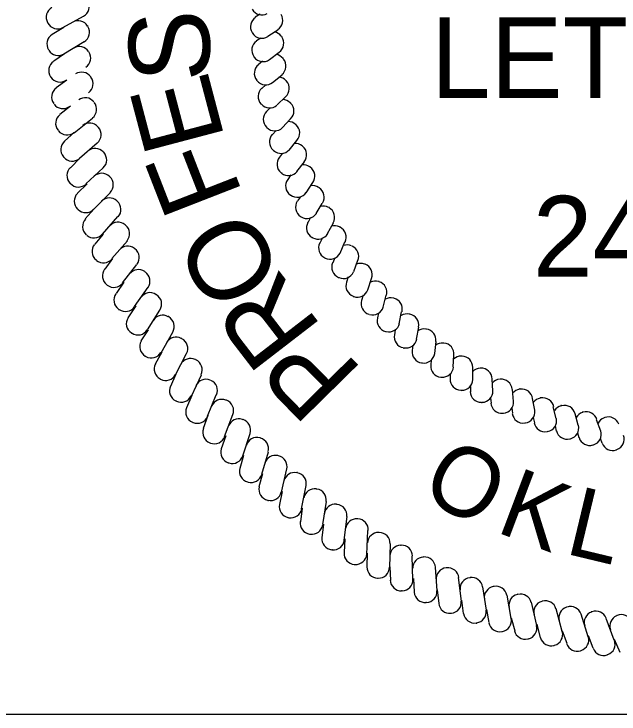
# Model space of a CAD drawing. Extents: x 2121385 to 2181200, y 132498 to 161273.
# Drawn here: x 2164147 to 2165083, y 136441 to 137524 of the extents above; entities that cross this region are included whole.
import ezdxf

# ---------------------------------------------------------------- set-up
doc = ezdxf.new("R2010")
doc.units = 0
doc.layers.add('SHT_Stamp_PE', color=7, linetype='Continuous')
doc.layers.add('SHT_Standard_Sheet_Lines', color=7, linetype='Continuous')

msp = doc.modelspace()

# ---------------------------------------------------------------- linework, layer by layer
at = {"layer": 'SHT_Stamp_PE'}
for p, q in [((2164528.1, 137523.1), (2164520.7, 137518.5)), ((2164222.8, 137502.9), (2164254.9, 137520.4)), ((2164199, 137510.3), (2164199.9, 137509.4)), ((2164224.6, 137502.9), (2164206.3, 137491.9)), ((2164262.2, 137504.8), (2164261.3, 137504.8)), ((2164516.1, 137494.7), (2164516.1, 137493.8)), ((2164540, 137489.2), (2164555.6, 137499.3)), ((2164224.6, 137461.7), (2164255.8, 137480.9)), ((2164529, 137486.4), (2164522.6, 137481.9)), ((2164562, 137488.3), (2164561.1, 137489.2)), ((2164200.8, 137468.1), (2164200.8, 137468.1)), ((2164225.6, 137461.7), (2164209.1, 137450.7)), ((2164518, 137458), (2164518.9, 137457.1)), ((2164542.7, 137453.4), (2164557.4, 137464.4)), ((2164531.7, 137450.7), (2164525.3, 137445.2)), ((2164563.8, 137454.4), (2164563.8, 137455.3)), ((2164203.6, 137426.9), (2164204.5, 137425.9)), ((2164547.3, 137417.7), (2164562, 137429.6)), ((2164229.2, 137421.4), (2164212.7, 137409.4)), ((2164522.6, 137421.4), (2164523.5, 137420.4)), ((2164537.2, 137414), (2164530.8, 137408.5)), ((2164569.3, 137419.5), (2164568.4, 137420.4)), ((2164554.6, 137382.9), (2164567.5, 137395.7)), ((2164209.1, 137384.7), (2164209.1, 137384.7)), ((2164234.7, 137381), (2164218.2, 137368.2)), ((2164529, 137384.7), (2164529.9, 137383.8)), ((2164575.7, 137385.6), (2164574.8, 137386.5)), ((2164543.6, 137378.3), (2164538.1, 137372.8)), ((2164240.2, 137339.8), (2164268.6, 137362.7)), ((2164562.9, 137348), (2164575.7, 137361.8)), ((2164277.8, 137348), (2164276.9, 137348.9)), ((2164584, 137352.6), (2164583.1, 137352.6)), ((2164215.5, 137343.4), (2164216.4, 137343.4)), ((2164241.1, 137340.7), (2164225.6, 137326.9)), ((2164538.1, 137348), (2164539.1, 137348)), ((2164552.8, 137343.4), (2164547.3, 137337)), ((2164573, 137313.2), (2164584.9, 137327.9)), ((2164248.5, 137300.4), (2164276, 137324.2)), ((2164594.1, 137318.7), (2164593.1, 137319.6)), ((2164286.1, 137309.5), (2164285.1, 137310.4)), ((2164548.2, 137313.2), (2164549.1, 137312.3)), ((2164562.9, 137308.6), (2164558.3, 137302.2)), ((2164223.7, 137302.2), (2164224.6, 137302.2)), ((2164249.4, 137300.4), (2164234.7, 137285.7)), ((2164584.9, 137280.2), (2164596.8, 137294.9)), ((2164258.6, 137260.9), (2164285.1, 137285.7)), ((2164606, 137286.6), (2164605.1, 137287.5)), ((2164561.1, 137278.4), (2164561.1, 137277.4)), ((2164575.7, 137274.7), (2164571.1, 137267.4)), ((2164296.1, 137271.9), (2164295.2, 137271.9)), ((2164599.6, 137247.2), (2164609.6, 137262.8)), ((2164233.8, 137261.9), (2164234.7, 137260.9)), ((2164260.4, 137260.9), (2164245.7, 137246.3)), ((2164619.7, 137254.5), (2164618.8, 137255.4)), ((2164270.5, 137221.5), (2164296.1, 137247.2)), ((2164574.8, 137243.5), (2164575.7, 137243.5)), ((2164590.4, 137240.8), (2164585.8, 137234.4)), ((2164307.1, 137234.4), (2164306.2, 137234.4)), ((2164615.1, 137215.1), (2164624.3, 137230.7)), ((2164245.7, 137222.4), (2164246.6, 137221.5)), ((2164271.4, 137222.4), (2164257.6, 137206.9)), ((2164635.3, 137224.3), (2164634.4, 137224.3)), ((2164284.2, 137183), (2164308.1, 137210.5)), ((2164591.3, 137210.5), (2164591.3, 137209.6)), ((2164606, 137208.7), (2164602.3, 137201.4)), ((2164320, 137196.8), (2164319.1, 137197.7)), ((2164632.6, 137183.9), (2164641.7, 137200.4)), ((2164651.8, 137194), (2164650.9, 137194)), ((2164259.5, 137182.1), (2164259.5, 137182.1)), ((2164285.1, 137183), (2164272.3, 137167.4)), ((2164608.7, 137178.4), (2164609.6, 137177.5)), ((2164624.3, 137176.6), (2164620.6, 137169.3)), ((2164298.9, 137145.4), (2164322.7, 137172.9)), ((2164651.8, 137153.7), (2164659.1, 137171.1)), ((2164670.1, 137164.7), (2164670.1, 137164.7)), ((2164334.6, 137160.1), (2164333.7, 137161)), ((2164274.1, 137143.6), (2164275.1, 137142.7)), ((2164299.8, 137145.4), (2164287.9, 137128.9)), ((2164628, 137146.4), (2164628.9, 137146.4)), ((2164643.6, 137146.4), (2164640.8, 137139)), ((2164315.4, 137107.9), (2164337.4, 137136.3)), ((2164672.9, 137125.3), (2164679.3, 137142.7)), ((2164690.3, 137136.3), (2164689.4, 137137.2)), ((2164350.2, 137124.4), (2164350.2, 137125.3)), ((2164649.1, 137116.1), (2164650.9, 137116.1)), ((2164664.6, 137117), (2164661.9, 137108.8)), ((2164694.9, 137096.9), (2164700.4, 137114.3)), ((2164290.6, 137105.1), (2164291.6, 137104.2)), ((2164317.2, 137108.8), (2164305.3, 137091.4)), ((2164333.7, 137071.2), (2164354.8, 137101.4)), ((2164712.3, 137109.7), (2164711.4, 137109.7)), ((2164367.6, 137089.5), (2164366.7, 137089.5)), ((2164672, 137086.8), (2164672.9, 137086.8)), ((2164687.6, 137088.6), (2164684.8, 137080.4)), ((2164718.7, 137070.3), (2164723.3, 137088.6)), ((2164735.2, 137084), (2164734.3, 137084)), ((2164335.6, 137072.1), (2164323.6, 137053.8)), ((2164309, 137066.6), (2164309.9, 137066.6)), ((2164353.9, 137035.4), (2164373.1, 137065.7)), ((2164696.7, 137059.3), (2164696.7, 137059.3)), ((2164711.4, 137061.1), (2164709.6, 137053.8)), ((2164743.5, 137044.6), (2164747.1, 137062.9)), ((2164760, 137059.3), (2164759.1, 137059.3)), ((2164386.9, 137055.6), (2164386, 137055.6)), ((2164354.8, 137035.4), (2164343.8, 137018)), ((2164737.1, 137035.4), (2164736.1, 137027.2)), ((2164770.1, 137020.8), (2164773.7, 137039.1)), ((2164785.6, 137036.4), (2164784.7, 137036.4)), ((2164329.1, 137029.9), (2164330.1, 137029.9)), ((2164375, 136999.7), (2164393.3, 137031.8)), ((2164722.4, 137032.7), (2164723.3, 137032.7)), ((2164407.1, 137021.7), (2164406.1, 137021.7)), ((2164798.5, 136998.8), (2164800.3, 137017.1)), ((2164812.2, 137014.4), (2164811.3, 137014.4)), ((2164749.9, 137007), (2164750.8, 137007)), ((2164764.6, 137011.6), (2164763.6, 137003.4)), ((2164350.2, 136994.2), (2164351.1, 136994.2)), ((2164375.9, 137000.6), (2164365.8, 136982.3)), ((2164397, 136965.8), (2164414.4, 136998.8)), ((2164826.9, 136977.7), (2164827.8, 136996)), ((2164840.6, 136994.2), (2164839.7, 136994.2)), ((2164429.1, 136988.7), (2164428.1, 136989.6)), ((2164778.3, 136984.1), (2164779.2, 136984.1)), ((2164793, 136988.7), (2164792.1, 136980.4)), ((2164857.1, 136958.4), (2164857.1, 136976.8)), ((2164870, 136975.9), (2164869.1, 136975.9)), ((2164373.1, 136959.4), (2164374.1, 136958.4)), ((2164397.9, 136966.7), (2164389.6, 136947.4)), ((2164421.7, 136932.8), (2164437.3, 136965.8)), ((2164807.6, 136962.1), (2164808.6, 136962.1)), ((2164822.3, 136967.6), (2164822.3, 136959.4)), ((2164888.3, 136940.1), (2164887.4, 136959.4)), ((2164452, 136956.6), (2164451.1, 136957.5)), ((2164899.3, 136958.4), (2164899.3, 136958.4)), ((2164838.8, 136941), (2164839.7, 136941.9)), ((2164853.5, 136947.4), (2164853.5, 136939.2)), ((2164920.4, 136924.5), (2164918.6, 136942.9)), ((2164930.5, 136943.8), (2164929.6, 136943.8)), ((2164422.6, 136933.7), (2164414.4, 136914.4)), ((2164446.5, 136901.6), (2164460.2, 136934.6)), ((2164475.8, 136926.4), (2164474.9, 136926.4)), ((2164884.6, 136930), (2164885.6, 136921.8)), ((2164953.4, 136910.8), (2164949.7, 136929.1)), ((2164962.6, 136930), (2164961.6, 136930)), ((2164397.9, 136925.4), (2164398.8, 136925.4)), ((2164870.9, 136922.7), (2164871.8, 136922.7)), ((2164986.4, 136897.9), (2164981.8, 136916.3)), ((2164994.6, 136918.1), (2164993.7, 136918.1)), ((2164903.9, 136906.2), (2164904.8, 136906.2)), ((2164917.6, 136914.4), (2164918.6, 136906.2)), ((2165020.3, 136887.9), (2165015.7, 136905.3)), ((2165027.6, 136908), (2165026.7, 136908)), ((2164447.4, 136902.5), (2164440.1, 136882.4)), ((2164473.1, 136870.4), (2164485.9, 136904.4)), ((2164501.5, 136896.1), (2164500.6, 136897)), ((2164950.6, 136899.8), (2164952.5, 136891.5)), ((2165055.1, 136878.7), (2165048.7, 136896.1)), ((2165061.6, 136899.8), (2165060.6, 136898.9)), ((2164423.6, 136892.4), (2164424.5, 136891.5)), ((2164937.8, 136891.5), (2164938.7, 136891.5)), ((2164984.6, 136886.9), (2164986.4, 136878.7)), ((2164501.5, 136840.2), (2164512.5, 136875)), ((2164972.6, 136877.8), (2164973.6, 136878.7)), ((2165019.4, 136875.9), (2165021.2, 136868.6)), ((2164474.9, 136871.4), (2164467.6, 136851.2)), ((2164529, 136867.7), (2164528.1, 136868.6)), ((2165007.5, 136866.8), (2165008.4, 136866.8)), ((2165054.2, 136867.7), (2165057, 136860.4)), ((2164450.1, 136860.4), (2164451.1, 136860.4)), ((2165043.2, 136856.7), (2165044.1, 136857.6)), ((2164502.4, 136841.1), (2164496.9, 136820.9)), ((2164530.8, 136811.8), (2164540.9, 136846.6)), ((2164556.5, 136840.2), (2164555.6, 136841.1)), ((2165079, 136849.4), (2165079.9, 136850.3)), ((2164478.6, 136830.1), (2164479.5, 136829.2)), ((2164561.1, 136784.3), (2164569.3, 136820)), ((2164531.7, 136812.7), (2164526.2, 136792.5)), ((2164585.8, 136814.5), (2164584.9, 136814.5)), ((2164508.8, 136799.9), (2164509.7, 136799.9)), ((2164592.2, 136758.6), (2164599.6, 136794.4)), ((2164616.1, 136788.9), (2164615.1, 136788.9)), ((2164562, 136785.2), (2164558.3, 136765)), ((2164540, 136771.4), (2164540.9, 136771.4)), ((2164625.2, 136733.9), (2164630.7, 136769.6)), ((2164647.2, 136765), (2164646.3, 136765)), ((2164593.1, 136759.5), (2164590.4, 136738.4)), ((2164571.1, 136744.9), (2164572.1, 136744.9)), ((2164658.2, 136710), (2164662.8, 136746.7)), ((2164679.3, 136743), (2164678.4, 136743)), ((2164626.1, 136734.8), (2164623.4, 136713.7)), ((2164693.1, 136688), (2164694.9, 136724.7)), ((2164712.3, 136721.9), (2164711.4, 136721.9)), ((2164605.1, 136719.2), (2164606, 136719.2)), ((2164659.1, 136711.9), (2164658.2, 136690.8)), ((2164728.8, 136667.9), (2164729.7, 136704.5)), ((2164746.2, 136701.8), (2164745.3, 136701.8)), ((2164639, 136695.4), (2164639.9, 136695.4)), ((2164694, 136689.9), (2164693.1, 136668.8)), ((2164764.6, 136648.6), (2164763.6, 136685.3)), ((2164781.1, 136683.4), (2164780.1, 136683.4)), ((2164673.8, 136672.4), (2164674.7, 136672.4)), ((2164728.8, 136668.8), (2164729.7, 136647.7)), ((2164802.1, 136632.1), (2164799.4, 136667.9)), ((2164816.8, 136666.9), (2164815.9, 136666.9)), ((2164709.6, 136651.4), (2164710.5, 136651.4)), ((2164765.5, 136650.4), (2164766.4, 136629.4)), ((2164839.7, 136615.6), (2164835.1, 136652.3)), ((2164852.6, 136652.3), (2164852.6, 136651.4)), ((2164878.2, 136601.9), (2164872.7, 136637.6)), ((2164890.1, 136638.5), (2164889.2, 136638.5)), ((2164747.1, 136632.1), (2164748.1, 136632.1)), ((2164802.1, 136633), (2164804.9, 136611.9)), ((2164916.7, 136589), (2164910.3, 136624.8)), ((2164926.8, 136626.6), (2164925.9, 136625.7)), ((2164784.7, 136613.8), (2164785.6, 136613.8)), ((2164839.7, 136617.4), (2164842.5, 136596.4)), ((2164956.1, 136578), (2164947.9, 136613.8)), ((2164965.3, 136615.6), (2164964.4, 136615.6)), ((2164878.2, 136602.8), (2164881.9, 136582.6)), ((2164995.6, 136568.9), (2164986.4, 136603.7)), ((2165002.9, 136606.4), (2165002, 136606.4)), ((2164823.2, 136597.3), (2164824.1, 136597.3)), ((2165035.9, 136560.6), (2165024.9, 136595.4)), ((2165041.4, 136599.1), (2165040.5, 136599.1)), ((2165080.8, 136593.6), (2165079.9, 136593.6)), ((2164862.6, 136581.7), (2164863.6, 136581.7)), ((2164916.7, 136589.9), (2164922.2, 136569.8)), ((2165076.2, 136555.1), (2165063.4, 136589)), ((2164956.1, 136579.9), (2164961.6, 136558.8)), ((2164995.6, 136569.8), (2165002.9, 136550.5)), ((2164902.1, 136568.9), (2164903, 136568.9)), ((2165035.9, 136562.4), (2165043.2, 136543.2)), ((2164942.4, 136556.9), (2164943.3, 136557.9)), ((2164982.7, 136546.9), (2164983.6, 136547.8)), ((2165076.2, 136556.9), (2165084.5, 136536.8)), ((2165024, 136538.6), (2165024.9, 136539.5)), ((2165065.2, 136533.1), (2165066.1, 136533.1))]:
    msp.add_line(p, q, dxfattribs=at)
for centre, start, end in [((2164246.6, 137535.1), 298.8, 28.8), ((2164214.2, 137518.4), 118.8, 208.8), ((2164530.7, 137539.3), 209.4533, 299.4533), ((2164546.1, 137513.8), 302.5567, 32.5567), ((2164246.5, 137496.1), 31.2, 118.5854), ((2164530.3, 137503.9), 122.5567, 212.5567), ((2164214.7, 137517.6), 208.8, 298.8), ((2164247, 137495.3), 301.2, 31.2), ((2164215.3, 137477.2), 121.2, 211.2), ((2164530.8, 137503.1), 212.5567, 302.5567), ((2164547, 137479.2), 35.6601, 78.6922), ((2164532.3, 137467.8), 125.6601, 215.6601), ((2164547.6, 137478.4), 305.6601, 35.6601), ((2164248.5, 137456.2), 33.6, 120.9854), ((2164215.8, 137476.4), 211.2, 301.2), ((2164249, 137455.4), 303.6, 33.6), ((2164532.8, 137467), 215.6601, 305.6601), ((2164550.3, 137444), 38.7635, 81.7956), ((2164218.1, 137436.1), 123.6, 213.6), ((2164550.9, 137443.2), 308.7635, 38.7635), ((2164536.2, 137431.8), 128.7635, 218.7635), ((2164218.6, 137435.3), 213.6, 303.6), ((2164252.1, 137416.5), 36, 123.3854), ((2164252.6, 137415.7), 306, 36), ((2164555.5, 137409), 41.8669, 84.899), ((2164536.8, 137431), 218.7635, 308.7635), ((2164556.2, 137408.3), 311.8669, 41.8669), ((2164222.6, 137395.1), 126, 216), ((2164542.1, 137396), 131.8669, 221.8669), ((2164257.4, 137377), 38.4, 125.7854), ((2164223.1, 137394.3), 216, 306), ((2164258, 137376.2), 308.4, 38.4), ((2164542.8, 137395.3), 221.8669, 311.8669), ((2164562.6, 137374.3), 44.9703, 88.0024), ((2164563.3, 137373.7), 314.9703, 44.9703), ((2164550, 137360.7), 134.9703, 224.9703), ((2164228.8, 137354.3), 128.4, 218.4), ((2164264.3, 137337.7), 40.8, 128.1854), ((2164571.6, 137340.1), 48.0737, 91.1058), ((2164572.3, 137339.5), 318.0737, 48.0737), ((2164229.4, 137353.6), 218.4, 308.4), ((2164265, 137336.9), 310.8, 40.8), ((2164550.6, 137360), 224.9703, 314.9703), ((2164236.7, 137313.9), 130.8, 220.8), ((2164559.7, 137325.8), 138.0737, 228.0737), ((2164582.4, 137306.4), 51.1771, 94.2092), ((2164583.1, 137305.8), 321.1771, 51.1771), ((2164272.9, 137298.7), 43.2, 130.5854), ((2164273.6, 137298), 313.2, 43.2), ((2164560.4, 137325.1), 228.0737, 318.0737), ((2164237.3, 137313.2), 220.8, 310.8), ((2164571.3, 137291.4), 141.1771, 231.1771), ((2164246.3, 137273.8), 133.2, 223.2), ((2164595, 137273.3), 54.2805, 97.3126), ((2164595.8, 137272.8), 324.2805, 54.2805), ((2164283.1, 137260.1), 45.6, 132.9854), ((2164572, 137290.8), 231.1771, 321.1771), ((2164283.8, 137259.5), 315.6, 45.6), ((2164584.7, 137257.8), 144.2805, 234.2805), ((2164247, 137273.1), 223.2, 313.2), ((2164609.4, 137241), 57.3839, 100.416), ((2164610.2, 137240.5), 327.3839, 57.3839), ((2164257.6, 137234.1), 135.6, 225.6), ((2164585.5, 137257.3), 234.2805, 324.2805), ((2164294.9, 137222), 48, 135.3854), ((2164295.7, 137221.4), 318, 48), ((2164600, 137224.9), 147.3839, 237.3839), ((2164258.3, 137233.5), 225.6, 315.6), ((2164625.5, 137209.5), 60.4873, 103.5194), ((2164626.4, 137209.1), 330.4873, 60.4873), ((2164600.8, 137224.4), 237.3839, 327.3839), ((2164270.5, 137195), 138, 228), ((2164308.3, 137184.5), 50.4, 137.7854), ((2164309.1, 137183.9), 320.4, 50.4), ((2164617, 137193), 150.4873, 240.4873), ((2164643.3, 137178.9), 63.5907, 106.6228), ((2164644.2, 137178.5), 333.5907, 63.5907), ((2164271.2, 137194.3), 228, 318), ((2164617.8, 137192.5), 240.4873, 330.4873), ((2164285.1, 137156.4), 140.4, 230.4), ((2164323.3, 137147.5), 52.8, 140.1854), ((2164635.7, 137161.9), 153.5907, 243.5907), ((2164662.8, 137149.4), 66.6941, 109.7262), ((2164663.6, 137149), 336.6941, 66.6941), ((2164324.1, 137146.9), 322.8, 52.8), ((2164636.5, 137161.5), 243.5907, 333.5907), ((2164285.8, 137155.8), 230.4, 320.4), ((2164656, 137132), 156.6941, 246.6941), ((2164683.8, 137120.9), 69.7975, 112.8296), ((2164684.6, 137120.6), 339.7975, 69.7975), ((2164301.2, 137118.5), 142.8, 232.8), ((2164339.8, 137111.2), 55.2, 142.5854), ((2164340.6, 137110.6), 325.2, 55.2), ((2164656.9, 137131.6), 246.6941, 336.6941), ((2164706.3, 137093.6), 72.9009, 115.933), ((2164302, 137117.9), 232.8, 322.8), ((2164678, 137103.2), 159.7975, 249.7975), ((2164707.2, 137093.3), 342.9009, 72.9009), ((2164319, 137081.3), 145.2, 235.2), ((2164357.8, 137075.6), 57.6, 144.9854), ((2164358.6, 137075), 327.6, 57.6), ((2164678.9, 137102.8), 249.7975, 339.7975), ((2164701.5, 137075.6), 162.9009, 252.9009), ((2164730.2, 137067.6), 76.0043, 119.0364), ((2164731.1, 137067.3), 346.0043, 76.0043), ((2164319.8, 137080.7), 235.2, 325.2), ((2164702.4, 137075.3), 252.9009, 342.9009), ((2164377.3, 137040.7), 60, 147.3854), ((2164755.5, 137042.8), 79.1077, 122.1398), ((2164756.5, 137042.7), 349.1077, 79.1077), ((2164338.2, 137044.8), 147.6, 237.6), ((2164378.1, 137040.3), 330, 60), ((2164726.4, 137049.3), 166.0043, 256.0043), ((2164339.1, 137044.3), 237.6, 327.6), ((2164727.3, 137049.1), 256.0043, 346.0043), ((2164782.2, 137019.5), 82.2111, 125.2432), ((2164783.1, 137019.4), 352.2111, 82.2111), ((2164398.2, 137006.8), 62.4, 149.7854), ((2164752.7, 137024.4), 169.1077, 259.1077), ((2164359, 137009.2), 150, 240), ((2164399.1, 137006.3), 332.4, 62.4), ((2164753.7, 137024.2), 259.1077, 349.1077), ((2164810, 136997.7), 85.3145, 128.3466), ((2164811, 136997.6), 355.3145, 85.3145), ((2164780.4, 137001), 172.2111, 262.2111), ((2164359.9, 137008.7), 240, 330), ((2164781.3, 137000.9), 262.2111, 352.2111), ((2164839, 136977.4), 88.4179, 131.45), ((2164840, 136977.4), 358.4179, 88.4179), ((2164381.3, 136974.5), 152.4, 242.4), ((2164420.5, 136973.7), 64.8, 152.1854), ((2164421.4, 136973.3), 334.8, 64.8), ((2164809.2, 136979.1), 175.3145, 265.3145), ((2164810.2, 136979), 265.3145, 355.3145), ((2164869.1, 136958.8), 91.5213, 134.5534), ((2164870, 136958.8), 1.5213, 91.5213), ((2164382.1, 136974), 242.4, 332.4), ((2164839.2, 136958.8), 178.4179, 268.4179), ((2164900.1, 136941.7), 94.6247, 137.6568), ((2164901, 136941.8), 4.6247, 94.6247), ((2164405, 136940.7), 154.8, 244.8), ((2164444.2, 136941.6), 67.2, 154.5854), ((2164445.1, 136941.2), 337.2, 67.2), ((2164840.2, 136958.8), 268.4179, 358.4179), ((2164870.3, 136940.2), 181.5213, 271.5213), ((2164871.2, 136940.2), 271.5213, 1.5213), ((2164932, 136926.4), 97.7281, 140.7602), ((2164932.9, 136926.5), 7.7281, 97.7281), ((2164405.8, 136940.3), 244.8, 334.8), ((2164469.2, 136910.5), 69.6, 156.9854), ((2164964.7, 136912.8), 100.8315, 143.8636), ((2164965.6, 136913), 10.8315, 100.8315), ((2164470.1, 136910.2), 339.6, 69.6), ((2164902.3, 136923.2), 184.6247, 274.6247), ((2164903.3, 136923.3), 274.6247, 4.6247), ((2164998, 136901.1), 103.9349, 146.967), ((2164998.9, 136901.3), 13.9349, 103.9349), ((2164430.1, 136908), 157.2, 247.2), ((2164935.2, 136908.1), 187.7281, 277.7281), ((2164936.1, 136908.2), 277.7281, 7.7281), ((2165032, 136891.1), 107.0383, 150.0704), ((2165032.9, 136891.4), 17.0383, 107.0383), ((2164430.9, 136907.7), 247.2, 337.2), ((2164495.5, 136880.5), 72, 159.3854), ((2164496.4, 136880.2), 342, 72), ((2164969.8, 136894.9), 280.8315, 10.8315), ((2165066.4, 136883), 110.1417, 153.1738), ((2165067.3, 136883.3), 20.1417, 110.1417), ((2164968.9, 136894.7), 190.8315, 280.8315), ((2165004.1, 136883.4), 283.9349, 13.9349), ((2164456.5, 136876.4), 159.6, 249.6), ((2165003.2, 136883.1), 193.9349, 283.9349), ((2165039, 136873.8), 287.0383, 17.0383), ((2164457.4, 136876.1), 249.6, 339.6), ((2164523.1, 136851.6), 74.4, 161.7854), ((2164524, 136851.4), 344.4, 74.4), ((2165038.1, 136873.5), 197.0383, 287.0383), ((2165074.4, 136866.1), 290.1417, 20.1417), ((2164484.2, 136845.9), 162, 252), ((2165073.5, 136865.7), 200.1417, 290.1417), ((2164485.1, 136845.6), 252, 342), ((2164551.8, 136824), 76.8, 164.1854), ((2164552.7, 136823.7), 346.8, 76.8), ((2164513.2, 136816.6), 164.4, 254.4), ((2164514.1, 136816.3), 254.4, 344.4), ((2164581.6, 136797.5), 79.2, 166.5854), ((2164582.5, 136797.3), 349.2, 79.2), ((2164543.4, 136788.5), 166.8, 256.8), ((2164612.5, 136772.3), 81.6, 168.9854), ((2164613.5, 136772.1), 351.6, 81.6), ((2164544.3, 136788.3), 256.8, 346.8), ((2164574.7, 136761.7), 169.2, 259.2), ((2164644.5, 136748.4), 84, 171.3854), ((2164645.4, 136748.3), 354, 84), ((2164575.7, 136761.5), 259.2, 349.2), ((2164677.4, 136725.9), 86.4, 173.7854), ((2164678.4, 136725.8), 356.4, 86.4), ((2164607.2, 136736.2), 171.6, 261.6), ((2164608.1, 136736.1), 261.6, 351.6), ((2164711.3, 136704.7), 88.8, 176.1854), ((2164712.2, 136704.7), 358.8, 88.8), ((2164640.6, 136712.2), 174, 264), ((2164641.6, 136712.1), 264, 354), ((2164746, 136685.1), 91.2, 178.5854), ((2164746.9, 136685.1), 1.2, 91.2), ((2164675.1, 136689.5), 176.4, 266.4), ((2164676, 136689.4), 266.4, 356.4), ((2164781.5, 136666.8), 93.6, 180.9854), ((2164782.4, 136666.9), 3.6, 93.6), ((2164710.5, 136668.3), 178.8, 268.8), ((2164711.4, 136668.3), 268.8, 358.8), ((2164817.7, 136650.1), 96, 183.3854), ((2164818.6, 136650.2), 6, 96), ((2164746.7, 136648.6), 181.2, 271.2), ((2164747.6, 136648.6), 271.2, 1.2), ((2164854.6, 136634.9), 98.4, 185.7854), ((2164855.5, 136635.1), 8.4, 98.4), ((2164892.1, 136621.3), 100.8, 188.1854), ((2164893, 136621.5), 10.8, 100.8), ((2164783.7, 136630.5), 183.6, 273.6), ((2164784.7, 136630.5), 273.6, 3.6), ((2164930.1, 136609.3), 103.2, 190.5854), ((2164931, 136609.5), 13.2, 103.2), ((2164822.4, 136614), 276, 6), ((2164968.6, 136598.8), 105.6, 192.9854), ((2164969.5, 136599.1), 15.6, 105.6), ((2164821.5, 136613.9), 186, 276), ((2165007.5, 136590), 108, 195.3854), ((2165008.4, 136590.3), 18, 108), ((2164859.9, 136598.9), 188.4, 278.4), ((2164860.8, 136599), 278.4, 8.4), ((2165046.8, 136582.8), 110.4, 197.7854), ((2165047.6, 136583.2), 20.4, 110.4), ((2165086.3, 136577.3), 112.8, 200.1854), ((2165087.1, 136577.7), 22.8, 112.8), ((2164898.9, 136585.5), 190.8, 280.8), ((2164899.8, 136585.7), 280.8, 10.8), ((2164938.4, 136573.8), 193.2, 283.2), ((2164939.3, 136574), 283.2, 13.2), ((2164978.4, 136563.7), 195.6, 285.6), ((2164979.3, 136564), 285.6, 15.6), ((2165019.6, 136555.6), 288, 18), ((2165018.7, 136555.3), 198, 288), ((2165060.3, 136549), 290.4, 20.4), ((2165059.4, 136548.7), 200.4, 290.4)]:
    msp.add_arc(centre, 17.1, start, end, dxfattribs=at)
at = {"layer": 'SHT_Standard_Sheet_Lines'}
msp.add_line((2158845.7, 136441.1), (2166182.5, 136441.1), dxfattribs=at)

# ---------------------------------------------------------------- texts
at = {"layer": 'SHT_Stamp_PE'}
for s, height, rotation, p in [('S', 125, 91.6471, (2164451.7, 137420)), ('E', 125, 104.781, (2164474.1, 137330)), ('F', 125, 111.2812, (2164502, 137244.8)), ('O', 125, 119.7819, (2164567, 137117.5)), ('R', 125, 127.622, (2164625.7, 137038)), ('P', 125, 134.5047, (2164689.3, 136971.5)), ('O', 107.2, 331.109, (2164772.2, 136779.7)), ('K', 107.2, 339.3098, (2164890.6, 136723.5)), ('L', 107.2, 346.5096, (2164997.6, 136689.8))]:
    msp.add_text(s, height=height, rotation=rotation, dxfattribs=at).set_placement(p)
for s, p in [('LETTNER', (2164792.1, 137393.6)), ('24224', (2164950, 137117.6))]:
    msp.add_text(s, height=124.67, dxfattribs=at).set_placement(p)

doc.saveas('drawing.dxf')
